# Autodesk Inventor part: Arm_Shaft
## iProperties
Company: Autodesk, Inc.
Shininess: 64.0
Length Units: 11269
Angle Units: 11279
Time Units: 11290
Mass Units: 11283
Length Display Precision: 3
Angle Display Precision: 2
Compacted: True
Part Number: Arm_Shaft
Document SubType Name: Modeling
Created: 2003-12
Catalog Web Link: www.autodesk.com
Vendor: Autodesk, Inc.
Designer: Administrator
Manufacturer: Standard
Standards Organization: Custom
Density: 1 g/cm^3
Density: 0.0
Volumn: 0.0
Area: 0.0
PropertySet Name: Model Information
Control State: 0
Master: False
Checked Out: False
Author: Administrator
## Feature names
1. Extrusion1
2. Extrusion2
3. Extrusion3
4. Extrusion4
5. Fillet1
